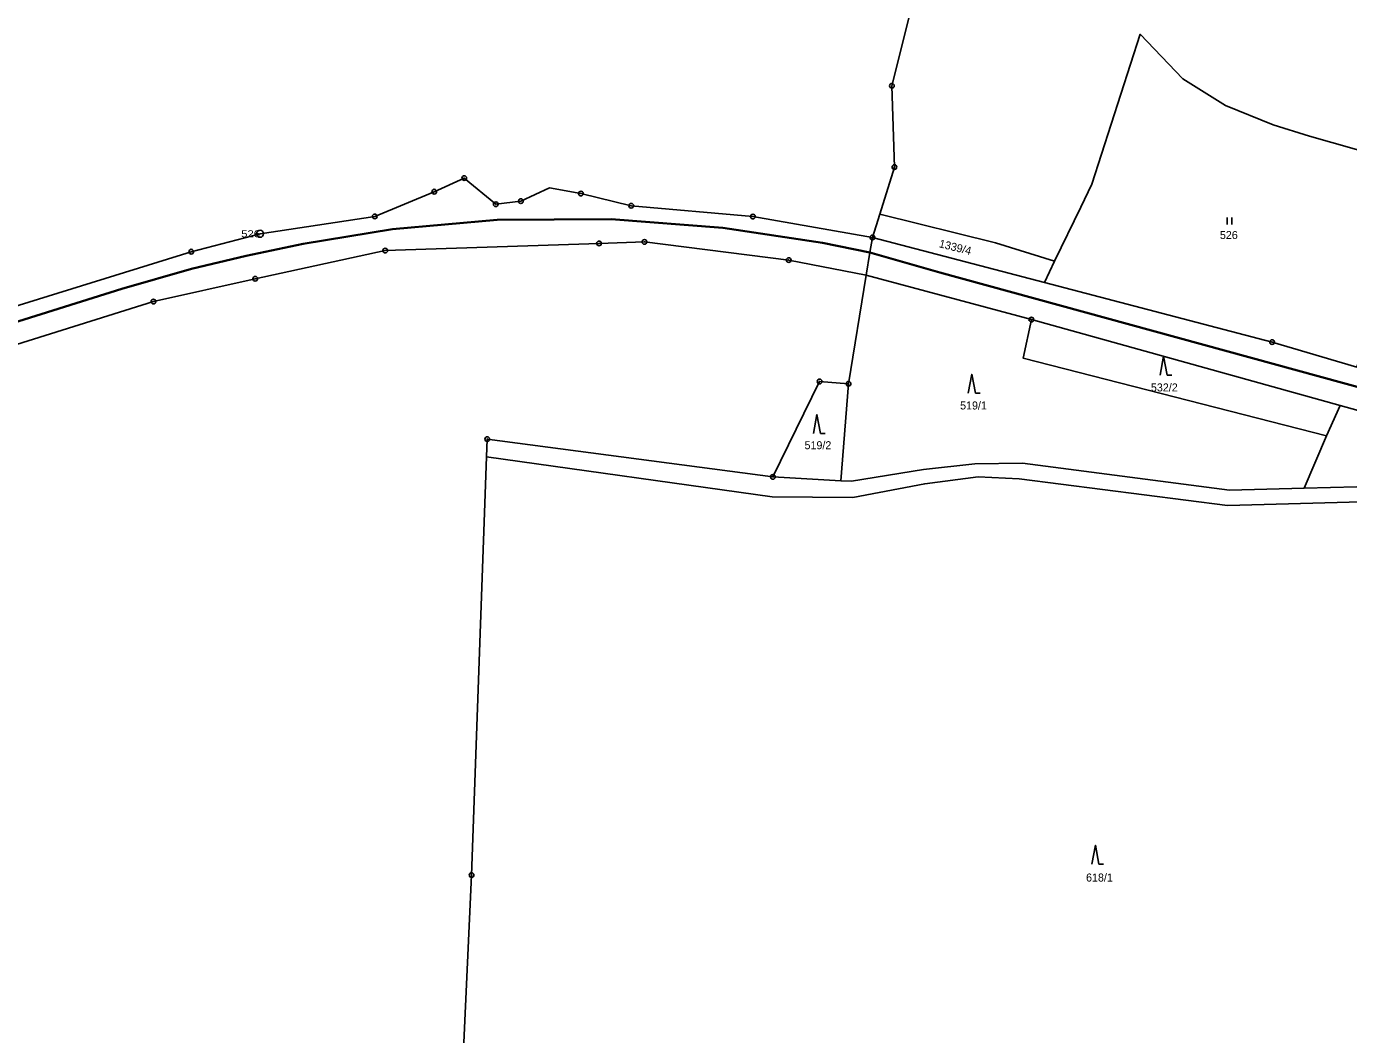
# Model space of a CAD drawing. Extents: x -872229 to -869198, y -1075981 to -1074329.
# Drawn here: x -870040 to -869759.2, y -1075531.8 to -1075317.7 of the extents above; entities that cross this region are included whole.
import ezdxf
from ezdxf.enums import TextEntityAlignment as Align

# ---------------------------------------------------------------- set-up
doc = ezdxf.new("R2010")
doc.units = 0
doc.header["$LTSCALE"] = 0.68
for name, color, linetype, lineweight in [('1', 7, 'Continuous', 25), ('3', 7, 'Continuous', 25), ('6', 7, 'Continuous', 25), ('8', 7, 'Continuous', 25)]:
    doc.layers.add(name, color=color, linetype=linetype, lineweight=lineweight)
doc.layers.add('2', color=7, linetype='Continuous')

msp = doc.modelspace()

# ---------------------------------------------------------------- linework, layer by layer
at = {"layer": '1'}
for p, q in [((-869858.81, -1075357.57), (-869860.35, -1075362.51)), ((-869823.79, -1075372.09), (-869860.35, -1075362.51)), ((-869826.6, -1075379.98), (-869861.67, -1075370.56)), ((-869760.99, -1075398.24), (-869826.6, -1075379.98)), ((-869865.43, -1075393.59), (-869867.09, -1075414.18)), ((-869694.77, -1075416.68), (-869760.99, -1075398.24)), ((-869763.88, -1075404.68), (-869768.68, -1075415.77))]:
    msp.add_line(p, q, dxfattribs=at)
for points in [[(-869786.75, -1075258.83), (-869811.82, -1075270.12), (-869821.36, -1075282.34), (-869814.57, -1075302.35), (-869843.97, -1075292.89), (-869846.6, -1075291.84), (-869856.2, -1075330.32)], [(-869742.8, -1075348.02), (-869767.51, -1075341.02), (-869775.27, -1075338.64), (-869785.4, -1075334.51), (-869794.46, -1075328.86), (-869803.48, -1075319.37), (-869813.74, -1075351.24), (-869816.07, -1075356.1), (-869821.67, -1075367.58)], [(-869856.2, -1075330.32), (-869855.68, -1075347.57), (-869858.81, -1075357.57)], [(-870067.91, -1075385.07), (-870005.01, -1075365.55), (-869990.41, -1075361.75), (-869966.05, -1075358.08), (-869953.4, -1075352.81), (-869947.04, -1075349.93), (-869940.35, -1075355.49), (-869935.02, -1075354.82), (-869928.93, -1075352), (-869922.26, -1075353.21), (-869911.58, -1075355.81), (-869885.74, -1075358.09), (-869860.35, -1075362.51)], [(-869821.67, -1075367.58), (-869823.79, -1075372.09), (-869775.47, -1075384.75), (-869757.47, -1075390.06), (-869742.8, -1075348.02)], [(-869858.81, -1075357.57), (-869834.21, -1075363.69), (-869821.67, -1075367.58)], [(-869861.67, -1075370.56), (-869878.14, -1075367.33), (-869908.77, -1075363.47), (-869918.42, -1075363.79), (-869963.81, -1075365.31), (-869991.44, -1075371.29), (-870013.06, -1075376.14), (-870080.98, -1075397.47), (-870137.41, -1075416.91), (-870198.36, -1075434.14), (-870229.56, -1075445.28), (-870312.6, -1075469.56), (-870365.19, -1075486.42), (-870398.17, -1075493.93), (-870445.72, -1075497.57), (-870473.49, -1075498.03), (-870483.95, -1075496.85)], [(-869860.35, -1075362.51), (-869860.88, -1075365.74), (-869861.67, -1075370.56)], [(-869881.5, -1075413.38), (-869871.59, -1075393.12), (-869865.43, -1075393.59), (-869861.67, -1075370.56)], [(-869826.6, -1075379.98), (-869828.36, -1075388.16), (-869763.88, -1075404.68), (-869760.99, -1075398.24)], [(-869942.3, -1075409.15), (-869942.16, -1075405.35), (-869881.5, -1075413.38)], [(-869956.21, -1075634.42), (-869950.93, -1075616.94), (-869945.48, -1075497.93), (-869942.3, -1075409.15)], [(-869633.9, -1075448.79), (-869640.35, -1075447.27), (-869661.71, -1075443.1), (-869696.29, -1075431.95), (-869735.78, -1075418.09), (-869784.91, -1075419.45), (-869829.22, -1075413.77), (-869837.88, -1075413.34), (-869849.23, -1075414.84), (-869864.5, -1075417.75), (-869881.67, -1075417.62), (-869942.3, -1075409.15)], [(-869768.68, -1075415.77), (-869784.54, -1075416.18), (-869828.48, -1075410.47), (-869838.61, -1075410.64), (-869849.53, -1075411.78), (-869864.81, -1075414.31), (-869867.09, -1075414.18), (-869881.5, -1075413.38)], [(-869693.4, -1075428.58), (-869694.91, -1075424.51), (-869690.98, -1075417.73), (-869694.77, -1075416.68), (-869700.66, -1075426.2), (-869735.08, -1075414.89), (-869768.68, -1075415.77)]]:
    msp.add_lwpolyline(points, dxfattribs=at)
at = {"layer": '3'}
for p, q in [((-869784.991, -1075359.78), (-869784.991, -1075358.28)), ((-869783.99, -1075359.78), (-869783.99, -1075358.28)), ((-869797.77, -1075391.77), (-869796.774, -1075391.77)), ((-869838.49, -1075395.58), (-869837.494, -1075395.58)), ((-869871.38, -1075404.14), (-869870.384, -1075404.14)), ((-869812.26, -1075495.59), (-869811.264, -1075495.59))]:
    msp.add_line(p, q, dxfattribs=at)
for points in [[(-869797.77, -1075391.77), (-869798.52, -1075387.77), (-869799.27, -1075391.77)], [(-869838.49, -1075395.58), (-869839.24, -1075391.58), (-869839.99, -1075395.58)], [(-869871.38, -1075404.14), (-869872.13, -1075400.14), (-869872.88, -1075404.14)], [(-869812.26, -1075495.59), (-869813.01, -1075491.59), (-869813.76, -1075495.59)]]:
    msp.add_lwpolyline(points, dxfattribs=at)
at = {"layer": '6', "lineweight": 35}
for p, q in [((-869981.25, -1075363.9), (-869962.25, -1075360.77)), ((-870019.78, -1075373.46), (-870004.94, -1075369.18))]:
    msp.add_line(p, q, dxfattribs=at)
for points in [[(-869962.25, -1075360.77), (-869940.06, -1075358.8), (-869915.83, -1075358.65), (-869892.09, -1075360.5), (-869870.97, -1075363.66), (-869860.88, -1075365.74)], [(-870004.94, -1075369.18), (-869993.36, -1075366.4), (-869981.25, -1075363.9)], [(-869860.88, -1075365.74), (-869846.01, -1075369.94), (-869704.43, -1075408.78), (-869641.66, -1075426.07), (-869625.84, -1075430.18), (-869607.72, -1075434.15), (-869580.2, -1075438.82), (-869542.66, -1075442.5), (-869518.18, -1075443.57), (-869485.71, -1075443.04), (-869459.17, -1075441.98), (-869409.77, -1075437.63)], [(-870103.28, -1075399.64), (-870067.42, -1075388.4), (-870019.78, -1075373.46)]]:
    msp.add_lwpolyline(points, dxfattribs=at)
at = {"layer": '8'}
for centre, radius in [((-869856.2, -1075330.3199), 0.5), ((-869856.2, -1075330.3199), 0.0303), ((-869855.68, -1075347.5699), 0.5), ((-869947.04, -1075349.9299), 0.5), ((-869947.04, -1075349.9299), 0.0303), ((-869855.68, -1075347.5699), 0.0303), ((-869953.4, -1075352.8099), 0.5), ((-869953.4, -1075352.8099), 0.0303), ((-869922.26, -1075353.2099), 0.5), ((-869940.35, -1075355.4899), 0.5), ((-869940.35, -1075355.4899), 0.0303), ((-869935.02, -1075354.8199), 0.5), ((-869935.02, -1075354.8199), 0.0303), ((-869922.26, -1075353.2099), 0.0303), ((-869911.58, -1075355.8099), 0.5), ((-869911.58, -1075355.8099), 0.0303), ((-869966.05, -1075358.0799), 0.5), ((-869966.05, -1075358.0799), 0.0303), ((-869885.74, -1075358.0899), 0.5), ((-869885.74, -1075358.0899), 0.0303), ((-869990.41, -1075361.7498), 0.75), ((-869990.41, -1075361.7498), 0.03), ((-869918.42, -1075363.7899), 0.5), ((-869918.42, -1075363.7899), 0.0303), ((-869908.77, -1075363.4699), 0.5), ((-869908.77, -1075363.4699), 0.0303), ((-869860.35, -1075362.5099), 0.5), ((-869860.35, -1075362.5099), 0.0303), ((-870005.01, -1075365.5499), 0.5), ((-870005.01, -1075365.5499), 0.0303), ((-869963.81, -1075365.3099), 0.5), ((-869963.81, -1075365.3099), 0.0303), ((-869878.14, -1075367.3299), 0.5), ((-869878.14, -1075367.3299), 0.0303), ((-869991.44, -1075371.2899), 0.5), ((-869991.44, -1075371.2899), 0.0303), ((-870013.06, -1075376.1399), 0.5), ((-870013.06, -1075376.1399), 0.0303), ((-869826.6, -1075379.9799), 0.5), ((-869826.6, -1075379.9799), 0.0303), ((-869775.47, -1075384.7499), 0.5), ((-869775.47, -1075384.7499), 0.0303), ((-869871.59, -1075393.1199), 0.5), ((-869871.59, -1075393.1199), 0.0303), ((-869865.43, -1075393.5899), 0.5), ((-869865.43, -1075393.5899), 0.0303), ((-869942.16, -1075405.3499), 0.5), ((-869942.16, -1075405.3499), 0.0303), ((-869881.5, -1075413.3799), 0.5), ((-869881.5, -1075413.3799), 0.0303), ((-869945.48, -1075497.9299), 0.5), ((-869945.48, -1075497.9299), 0.0303)]:
    msp.add_circle(centre, radius, dxfattribs=at)

# ---------------------------------------------------------------- texts
at = {"layer": '2'}
for s, p in [('526', (-869786.55, -1075362.86)), ('532/2', (-869801.2, -1075395.23)), ('519/1', (-869841.73, -1075399.06)), ('519/2', (-869874.77, -1075407.5)), ('618/1', (-869814.98, -1075499.31))]:
    msp.add_text(s, height=1.7, dxfattribs=at).set_placement(p)
msp.add_text('1339/4', height=1.7, rotation=346, dxfattribs=at).set_placement((-869846.335, -1075364.584))
at = {"layer": '8', "width": 1.2}
msp.add_text('526', height=1.5, dxfattribs=at).set_placement((-869990.41, -1075362.5), align=Align.RIGHT)

doc.saveas('drawing.dxf')
